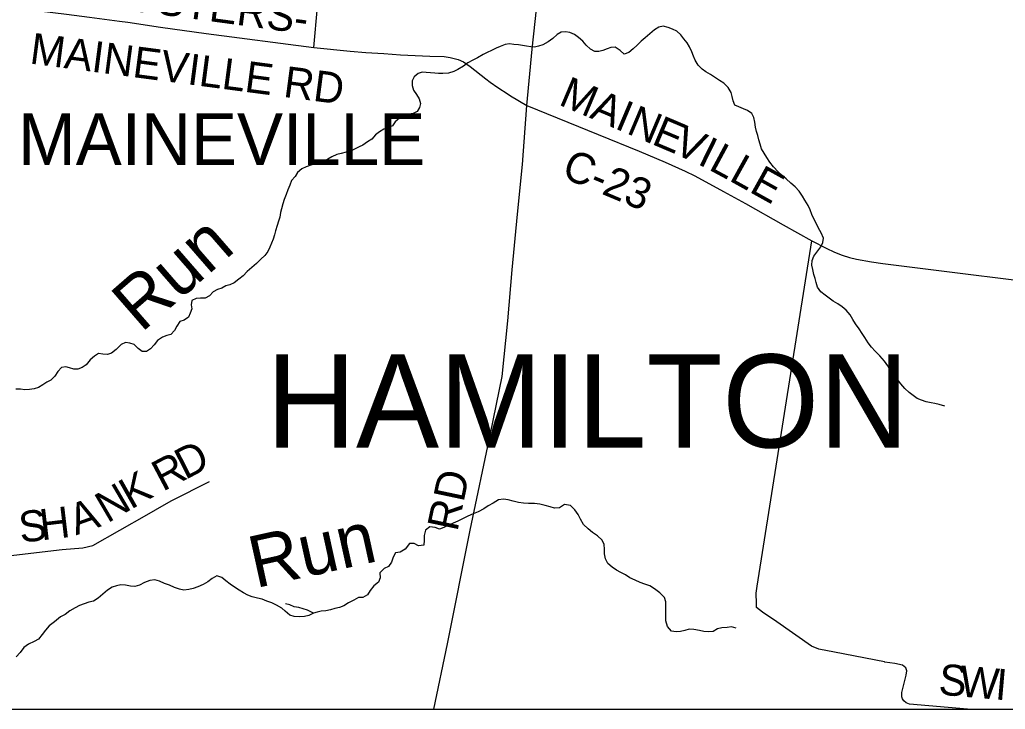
# Model space of a CAD drawing. Extents: x 0 to 34, y -4 to 22.
# Drawn here: x 5.809 to 7.08, y 14.1 to 14.989 of the extents above; entities that cross this region are included whole.
import ezdxf

# ---------------------------------------------------------------- set-up
doc = ezdxf.new("R2010")
doc.units = 0
for name, color, linetype in [('GM_X_City_Street', 7, 'Continuous'), ('GM_X_Corporation_Text', 7, 'Continuous'), ('GM_X_County_Road', 7, 'Continuous'), ('GM_X_County_Road_Text', 7, 'Continuous'), ('GM_X_Minor_River', 7, 'Continuous'), ('GM_X_Minor_River_Text', 7, 'Continuous'), ('GM_X_Township', 7, 'Continuous'), ('GM_X_Township_Road', 7, 'Continuous'), ('GM_X_Township_Road_Text', 7, 'Continuous'), ('GM_X_Township_Text', 7, 'Continuous'), ('SH_Data', 7, 'Continuous'), ('SN_P_Text', 7, 'Continuous')]:
    doc.layers.add(name, color=color, linetype=linetype)

msp = doc.modelspace()

# ---------------------------------------------------------------- linework, layer by layer
at = {"layer": 'GM_X_City_Street'}
msp.add_lwpolyline([(6.4154, 14.9087), (6.4252, 14.9017), (6.4387, 14.893)], dxfattribs=at)
at = {"layer": 'GM_X_County_Road'}
for points in [[(6.3429, 14.1), (6.3606, 14.1843), (6.3898, 14.3308), (6.4159, 14.4555), (6.4308, 14.5292), (6.4382, 14.601), (6.4439, 14.6664), (6.4506, 14.7382), (6.4572, 14.8025), (6.4628, 14.8785), (6.4698, 14.9511), (6.4849, 15.0904), (6.4899, 15.1382)], [(5.7764, 15.0074), (5.8511, 14.9985), (5.8688, 14.9964), (5.8988, 14.9925), (5.9375, 14.9873), (5.9481, 14.986), (5.9903, 14.9796), (6.0493, 14.9713), (6.1878, 14.9534), (6.2348, 14.9486), (6.255, 14.9467), (6.2785, 14.9453), (6.2999, 14.9438), (6.3378, 14.9422), (6.3562, 14.9415), (6.364, 14.9405), (6.3743, 14.9378), (6.3812, 14.9346), (6.3896, 14.9286), (6.4098, 14.9128), (6.4154, 14.9087)], [(6.4387, 14.893), (6.4415, 14.8911), (6.4628, 14.8785)], [(6.4628, 14.8785), (6.5547, 14.8412), (6.6077, 14.8194), (6.6413, 14.8053), (6.6669, 14.7937), (6.6794, 14.7878), (6.7165, 14.7674), (6.7447, 14.7519), (6.7934, 14.7245), (6.8305, 14.704), (6.8489, 14.6945), (6.8598, 14.6893), (6.8695, 14.6856), (6.8789, 14.6826), (6.888, 14.6803), (6.9075, 14.6768), (6.9219, 14.6747), (7.1841, 14.6419), (7.7118, 14.5899), (7.7213, 14.589)]]:
    msp.add_lwpolyline(points, dxfattribs=at)
at = {"layer": 'GM_X_Minor_River'}
for points in [[(7.0018, 14.4909), (6.9948, 14.4929), (6.9892, 14.4943), (6.9842, 14.4952), (6.978, 14.4964), (6.9719, 14.4984), (6.9663, 14.5006), (6.9611, 14.5047), (6.9558, 14.5085), (6.9502, 14.5137), (6.9453, 14.5194), (6.9411, 14.5253), (6.9361, 14.5318), (6.9314, 14.5372), (6.9283, 14.5429), (6.9241, 14.5486), (6.918, 14.5559), (6.9123, 14.5619), (6.9075, 14.567), (6.9031, 14.5724), (6.8986, 14.5795), (6.8952, 14.5846), (6.8913, 14.5903), (6.8869, 14.5968), (6.8835, 14.6027), (6.8799, 14.6084), (6.8746, 14.6146), (6.8696, 14.6187), (6.8638, 14.6228), (6.858, 14.6261), (6.8527, 14.6299), (6.8476, 14.6337), (6.8421, 14.6384), (6.8379, 14.6443), (6.8362, 14.6502), (6.8349, 14.6556), (6.8331, 14.6607), (6.8316, 14.6669), (6.8306, 14.6725), (6.831, 14.6787), (6.833, 14.6842), (6.8382, 14.6911), (6.842, 14.6961), (6.8448, 14.7017), (6.8454, 14.7073), (6.8423, 14.7143), (6.8389, 14.7205), (6.8361, 14.7267), (6.833, 14.7324), (6.8304, 14.738), (6.8281, 14.7439), (6.8255, 14.7496), (6.8216, 14.7566), (6.8185, 14.7617), (6.814, 14.768), (6.809, 14.7734), (6.8032, 14.7783), (6.7972, 14.7837), (6.7922, 14.7881), (6.7872, 14.793), (6.7811, 14.7995), (6.7764, 14.8052), (6.7722, 14.8114), (6.7688, 14.8168), (6.7657, 14.8227), (6.7637, 14.8284), (6.7622, 14.8343), (6.7606, 14.8397), (6.7591, 14.8448), (6.7579, 14.8504), (6.7567, 14.8571), (6.7554, 14.863), (6.7531, 14.8681), (6.7475, 14.8719), (6.7422, 14.8742), (6.7364, 14.8767), (6.7313, 14.8789), (6.729, 14.8845), (6.7278, 14.8899), (6.7265, 14.895), (6.7226, 14.9017), (6.7171, 14.9072), (6.7115, 14.9105), (6.706, 14.914), (6.6999, 14.9182), (6.6938, 14.9217), (6.6888, 14.9253), (6.684, 14.9304), (6.6799, 14.9369), (6.6778, 14.942), (6.6755, 14.9477), (6.6727, 14.9539), (6.6698, 14.9593), (6.6653, 14.9644), (6.6614, 14.9696), (6.6564, 14.9742), (6.6508, 14.9769), (6.6453, 14.9792), (6.6386, 14.9806), (6.633, 14.9796), (6.6276, 14.9762)], [(6.6276, 14.9762), (6.6213, 14.9707), (6.6156, 14.9657), (6.6102, 14.9613), (6.605, 14.9563), (6.6001, 14.9513), (6.5944, 14.9466), (6.5885, 14.9448), (6.583, 14.9494), (6.5769, 14.9535), (6.5713, 14.9533), (6.5662, 14.9516), (6.5608, 14.9495), (6.5557, 14.9482), (6.5503, 14.9481), (6.545, 14.9511), (6.5395, 14.9563), (6.5348, 14.9614), (6.5295, 14.9663), (6.5242, 14.9701), (6.5184, 14.9726), (6.5125, 14.9735), (6.5069, 14.9731), (6.5017, 14.97), (6.4963, 14.965), (6.4901, 14.9605), (6.4836, 14.9566), (6.4779, 14.9551), (6.4728, 14.9538), (6.4678, 14.9542), (6.4622, 14.9551), (6.4571, 14.9557), (6.4518, 14.9566), (6.4461, 14.9569), (6.4405, 14.9578), (6.4349, 14.9569), (6.4282, 14.9546), (6.4231, 14.9522), (6.4171, 14.9494), (6.4117, 14.9468), (6.4066, 14.9442), (6.3993, 14.94), (6.3931, 14.9369), (6.3866, 14.9333), (6.381, 14.9291), (6.3739, 14.9247), (6.3685, 14.9221), (6.3618, 14.9203), (6.3546, 14.9196), (6.349, 14.9197), (6.3439, 14.9201), (6.3385, 14.9204), (6.3327, 14.921), (6.3276, 14.9214), (6.3225, 14.9196), (6.3173, 14.9154), (6.3148, 14.9101), (6.315, 14.9042), (6.3165, 14.898), (6.3204, 14.8926), (6.3238, 14.8872), (6.3256, 14.8811), (6.3242, 14.8757), (6.3214, 14.8707), (6.316, 14.8681), (6.3106, 14.8671), (6.3047, 14.8656), (6.2985, 14.862), (6.2931, 14.8572), (6.2893, 14.8522), (6.2842, 14.8502), (6.2785, 14.8478), (6.2728, 14.8445), (6.2677, 14.8405), (6.263, 14.835), (6.2574, 14.8316), (6.2514, 14.8274), (6.2463, 14.8251), (6.2406, 14.822), (6.2352, 14.8197), (6.2299, 14.8181), (6.2234, 14.8166), (6.2178, 14.8151), (6.2113, 14.8123), (6.2062, 14.8094), (6.2008, 14.8068), (6.1957, 14.8053), (6.19, 14.8038), (6.1841, 14.8015), (6.1782, 14.7994), (6.1725, 14.7969), (6.1671, 14.7921), (6.1638, 14.7871), (6.1592, 14.7816), (6.1569, 14.7757), (6.1544, 14.7696), (6.1522, 14.7638), (6.1499, 14.7574), (6.148, 14.7518), (6.1463, 14.7454), (6.1451, 14.7404)], [(6.1451, 14.7404), (6.1442, 14.7345), (6.1425, 14.7294), (6.1408, 14.7238), (6.1386, 14.7169), (6.1372, 14.7119), (6.1357, 14.706), (6.1335, 14.701), (6.1313, 14.6957), (6.1285, 14.6901), (6.1247, 14.6851), (6.1195, 14.6803), (6.1141, 14.6748), (6.1078, 14.6696), (6.1019, 14.6643), (6.0967, 14.6588), (6.0913, 14.6546), (6.0853, 14.6499), (6.0796, 14.6473), (6.0745, 14.6458), (6.0694, 14.6429), (6.0638, 14.6411), (6.0581, 14.638), (6.0532, 14.633), (6.0478, 14.6299), (6.0416, 14.63), (6.036, 14.6298), (6.0304, 14.6272), (6.0297, 14.6216), (6.0307, 14.6162), (6.0285, 14.6107), (6.0263, 14.6054), (6.0208, 14.6017), (6.0152, 14.5999), (6.0111, 14.5938), (6.0083, 14.5883), (6.0034, 14.5833), (5.9983, 14.582), (5.9929, 14.5799), (5.9864, 14.5755), (5.9818, 14.57), (5.9772, 14.5647), (5.972, 14.5613), (5.9664, 14.5614), (5.9614, 14.5652), (5.9564, 14.5701), (5.9505, 14.5721), (5.9452, 14.5727), (5.9393, 14.5701), (5.9328, 14.5638), (5.9268, 14.5593), (5.9217, 14.5576), (5.9158, 14.5579), (5.9102, 14.5588), (5.9051, 14.5551), (5.8996, 14.5504), (5.8944, 14.5441), (5.8893, 14.5407), (5.8834, 14.5386), (5.8783, 14.5387), (5.873, 14.5404), (5.8679, 14.5413), (5.8623, 14.5408), (5.8579, 14.5356), (5.8538, 14.5295), (5.8489, 14.5242), (5.8435, 14.5219), (5.8384, 14.5182), (5.8327, 14.5148), (5.8271, 14.5131), (5.8212, 14.5121), (5.8153, 14.5119), (5.8097, 14.5125), (5.8035, 14.5126)], [(6.7327, 14.2046), (6.7266, 14.2063), (6.721, 14.2053), (6.7145, 14.2052), (6.7089, 14.2036), (6.703, 14.2003), (6.6973, 14.1998), (6.6912, 14.2002), (6.6853, 14.2016), (6.6784, 14.2028), (6.6722, 14.2034), (6.6666, 14.2016), (6.661, 14.2004), (6.6553, 14.1999), (6.6495, 14.2008), (6.6442, 14.2068), (6.6422, 14.2141), (6.642, 14.2197), (6.6421, 14.2264), (6.6422, 14.2325), (6.6421, 14.2384), (6.6403, 14.244), (6.6342, 14.2503), (6.6274, 14.2555), (6.6213, 14.259), (6.6149, 14.2613), (6.6088, 14.2635), (6.6024, 14.2663), (6.5955, 14.2696), (6.59, 14.2734), (6.5839, 14.2765), (6.5783, 14.2795), (6.5727, 14.2831), (6.5672, 14.288), (6.5641, 14.2939), (6.5629, 14.3003), (6.563, 14.3065), (6.5625, 14.3124), (6.5599, 14.318), (6.5541, 14.3235), (6.5475, 14.3281), (6.5417, 14.3325), (6.5359, 14.3382), (6.532, 14.3449), (6.5289, 14.3511), (6.5247, 14.3571), (6.519, 14.3628), (6.5112, 14.364), (6.5047, 14.3598), (6.4986, 14.3594), (6.493, 14.3608), (6.4863, 14.3628), (6.4794, 14.3645), (6.4727, 14.3651), (6.465, 14.3655), (6.4583, 14.3656), (6.4519, 14.3665), (6.4452, 14.3682), (6.4388, 14.3702), (6.4327, 14.3711), (6.426, 14.3699), (6.4192, 14.3657), (6.4128, 14.3623), (6.4071, 14.3584), (6.3998, 14.3545), (6.3936, 14.3519), (6.3868, 14.3488), (6.3796, 14.3455), (6.3736, 14.3426), (6.3677, 14.3401), (6.362, 14.3372), (6.3556, 14.3344), (6.3499, 14.3323), (6.3443, 14.3343), (6.3377, 14.3352), (6.332, 14.331), (6.3303, 14.3241), (6.3304, 14.3182), (6.3298, 14.3118), (6.3231, 14.3106), (6.3175, 14.3136), (6.3116, 14.3137), (6.3056, 14.3066), (6.2994, 14.3026), (6.2935, 14.3017), (6.2902, 14.2961), (6.288, 14.2897), (6.2844, 14.2842), (6.2787, 14.2816), (6.2733, 14.2758), (6.2735, 14.2696), (6.2715, 14.2638), (6.2655, 14.2593), (6.2606, 14.2533), (6.2573, 14.2477), (6.2514, 14.2441), (6.2455, 14.2439), (6.2395, 14.2408), (6.2328, 14.2371), (6.2268, 14.2335), (6.2212, 14.2314)], [(6.1465, 14.2302), (6.1397, 14.2341), (6.1336, 14.2374), (6.1274, 14.2396), (6.1213, 14.2418), (6.1152, 14.2433), (6.1085, 14.245), (6.1027, 14.2472), (6.0971, 14.2502), (6.0916, 14.2535), (6.0857, 14.2574), (6.0802, 14.2612), (6.0746, 14.2656), (6.0691, 14.2697), (6.0627, 14.2719), (6.0568, 14.2685), (6.0511, 14.2643), (6.0451, 14.261), (6.0384, 14.2579), (6.0322, 14.2558), (6.0266, 14.2546), (6.0204, 14.2536), (6.0148, 14.2548), (6.0084, 14.257), (6.0018, 14.2598), (5.9954, 14.2623), (5.989, 14.2651), (5.9829, 14.2668), (5.9765, 14.2661), (5.9695, 14.2635), (5.9633, 14.2601), (5.9571, 14.2581), (5.9515, 14.2587), (5.9451, 14.2599), (5.939, 14.2605), (5.9333, 14.2593), (5.9277, 14.2575), (5.9217, 14.2536), (5.9157, 14.2483), (5.9098, 14.2433), (5.9038, 14.2394), (5.8977, 14.2379), (5.8915, 14.2361), (5.8858, 14.2338), (5.8799, 14.2307), (5.8734, 14.2268), (5.8672, 14.2223), (5.8612, 14.219), (5.8534, 14.2127), (5.8466, 14.2077), (5.842, 14.2019), (5.8376, 14.1963), (5.8329, 14.1905), (5.827, 14.1872), (5.82, 14.1841), (5.8138, 14.1796), (5.8091, 14.173), (5.8039, 14.1675)], [(6.1874, 14.2237), (6.1817, 14.2208), (6.1761, 14.2196), (6.1694, 14.2194), (6.1627, 14.2195), (6.1571, 14.2212), (6.151, 14.2264), (6.1465, 14.2302)], [(6.1874, 14.2237), (6.1799, 14.2278), (6.1741, 14.2295), (6.1685, 14.2312), (6.1626, 14.2321), (6.1571, 14.2346), (6.1515, 14.236)], [(6.2212, 14.2314), (6.215, 14.2299), (6.2094, 14.2284), (6.2035, 14.2269), (6.1973, 14.2265), (6.1925, 14.2253), (6.1874, 14.2237)]]:
    msp.add_lwpolyline(points, dxfattribs=at)
at = {"layer": 'GM_X_Township'}
msp.add_lwpolyline([(3.8794, 14.1), (7.6703, 14.1), (7.7118, 14.5899), (7.7699, 14.9905), (7.8078, 15.2433), (7.8116, 15.2993), (7.8125, 15.3129), (7.8465, 15.6298), (7.8833, 16.0418)], dxfattribs=at)
at = {"layer": 'GM_X_Township_Road'}
for points in [[(6.1878, 14.9534), (6.1927, 15.0058), (6.1944, 15.0195), (6.1969, 15.0264), (6.201, 15.0316), (6.2063, 15.0353), (6.2163, 15.0405), (6.2422, 15.0517), (6.2896, 15.0728), (6.4738, 15.1588), (6.4897, 15.1666), (6.4932, 15.1709), (6.4952, 15.172)], [(6.9241, 14.161), (6.8597, 14.1735), (6.8396, 14.1777), (6.8301, 14.1814), (6.7854, 14.2126), (6.7669, 14.225), (6.7592, 14.2312), (6.7591, 14.2362), (6.7588, 14.2499), (6.7599, 14.2587), (6.8305, 14.704)], [(5.9949, 14.3635), (6.005, 14.3692), (6.0536, 14.3938)], [(5.7853, 14.2969), (5.7865, 14.297), (5.8634, 14.3059), (5.8898, 14.308), (5.9028, 14.3112), (5.9727, 14.3507), (5.9949, 14.3635)], [(7.0312, 14.1), (6.9566, 14.1065), (6.9523, 14.1081), (6.9493, 14.1109), (6.9475, 14.1135), (6.9465, 14.1159), (6.9464, 14.1217), (6.9522, 14.1438), (6.953, 14.1495), (6.9518, 14.1533), (6.9476, 14.157), (6.9377, 14.159), (6.9248, 14.1609), (6.9241, 14.161)]]:
    msp.add_lwpolyline(points, dxfattribs=at)
at = {"layer": 'SH_Data'}
msp.add_line((2.1, 14.1), (8.9, 14.1), dxfattribs=at)
at = {"layer": 'SN_P_Text'}
msp.add_lwpolyline([(8.9, 14.1), (8.9, 20.9), (2.1, 20.9), (2.1, 14.1)], close=True, dxfattribs=at)

# ---------------------------------------------------------------- texts
at = {"layer": 'GM_X_Corporation_Text'}
msp.add_text('MAINEVILLE', height=0.06667, rotation=0, dxfattribs=at).set_placement((5.8065, 14.8016))
at = {"layer": 'GM_X_County_Road_Text'}
for s, rotation, p in [('FOSTERS-', 352.2881, (5.9103, 15.0066)), ('MAINEVILLE RD', 352.5151, (5.8204, 14.9327)), ('M', 337.0593, (6.5024, 14.88)), ('A', 337.0587, (6.5424, 14.8631)), ('I', 337.0577, (6.5748, 14.8494)), ('N', 337.0587, (6.59, 14.843)), ('E', 337.0501, (6.6224, 14.8293)), ('V', 336.005, (6.6497, 14.8177)), ('I', 333.8399, (6.6815, 14.8035)), ('L', 331.7213, (6.6959, 14.7965)), ('C-23', 337.3321, (6.5059, 14.7867)), ('L', 330.9791, (6.7222, 14.7824)), ('E', 330.9733, (6.7483, 14.7678)), ('RD', 78.1137, (6.3731, 14.3281))]:
    msp.add_text(s, height=0.04, rotation=rotation, dxfattribs=at).set_placement(p)
at = {"layer": 'GM_X_Minor_River_Text'}
for rotation, p in [(41.0445, (5.9652, 14.5845)), (12.4722, (6.1127, 14.256))]:
    msp.add_text('Run', height=0.06666, rotation=rotation, dxfattribs=at).set_placement(p)
at = {"layer": 'GM_X_Township_Road_Text'}
for s, rotation, p in [('D', 26.9935, (6.022, 14.3955)), ('R', 27.8376, (5.9931, 14.3802)), ('K', 29.4905, (5.9519, 14.3571)), ('N', 30.4062, (5.9217, 14.3394)), ('A', 19.618, (5.8811, 14.3241)), ('S', 6.7484, (5.8098, 14.3146)), ('H', 6.7839, (5.8367, 14.3177)), ('S', 355.0714, (6.993, 14.1191)), ('W', 355.0752, (7.0199, 14.1167)), ('I', 355.0762, (7.066, 14.1128))]:
    msp.add_text(s, height=0.04, rotation=rotation, dxfattribs=at).set_placement(p)
at = {"layer": 'GM_X_Township_Text'}
msp.add_text('HAMILTON', height=0.12, rotation=0, dxfattribs=at).set_placement((6.1266, 14.4375))

doc.saveas('drawing.dxf')
